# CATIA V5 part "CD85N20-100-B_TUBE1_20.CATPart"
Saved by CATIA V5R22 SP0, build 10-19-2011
Part number: CD85N20-100-B_TUBE1_20
Revision: ANY
Definition: UNKNOWN
Nomenclature: CD85N20-100-B_TUBE1_20
Source: Unknown
Bounding box of the stored display mesh (mm): x -10.8 to 10.8, y -10.8 to 10.636, z -66 to 66
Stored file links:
  U:\S9A\PER\CAO\Assemblage\Reservoir_Flacon\Verin\Poussoir_2\CD85N20-100-B_TUBE1_20.CATPart
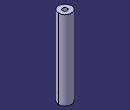
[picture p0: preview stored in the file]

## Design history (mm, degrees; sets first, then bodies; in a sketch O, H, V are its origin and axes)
Body1 "CHAMBER" (main body)
  Solid1: solid without history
